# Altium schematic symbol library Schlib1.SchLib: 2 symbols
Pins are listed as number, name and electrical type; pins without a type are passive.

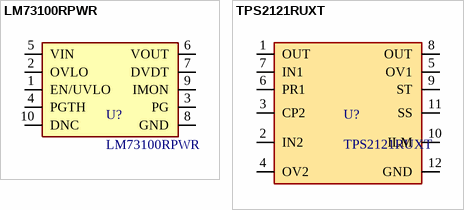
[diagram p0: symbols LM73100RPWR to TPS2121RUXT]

## LM73100RPWR
designator U?
28.4mV 44.85mΩ VQFN-10-HR(2x2) OR Controllers, Ideal Diodes RoHS; Manufacturer: TI
footprint LM73100RPWR (28.4mV 44.85mΩ VQFN-10-HR(2x2) OR Controllers, Ideal Diodes RoHS)
pins: 1 EN/UVLO, 2 OVLO, 3 PG, 4 PGTH, 5 VIN, 6 VOUT, 7 DVDT, 8 GND, 9 IMON, 10 DNC

## TPS2121RUXT
designator U?
2.8V~22V 2 VQFN-HR-12(2x2.5) OR Controllers, Ideal Diodes RoHS; Manufacturer: TI
footprint TPS2121RUXT (2.8V~22V 2 VQFN-HR-12(2x2.5) OR Controllers, Ideal Diodes RoHS)
pins: 1 OUT, 2 IN2, 3 CP2, 4 OV2, 5 OV1, 6 PR1, 7 IN1, 8 OUT, 9 ST, 10 ILM, 11 SS, 12 GND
